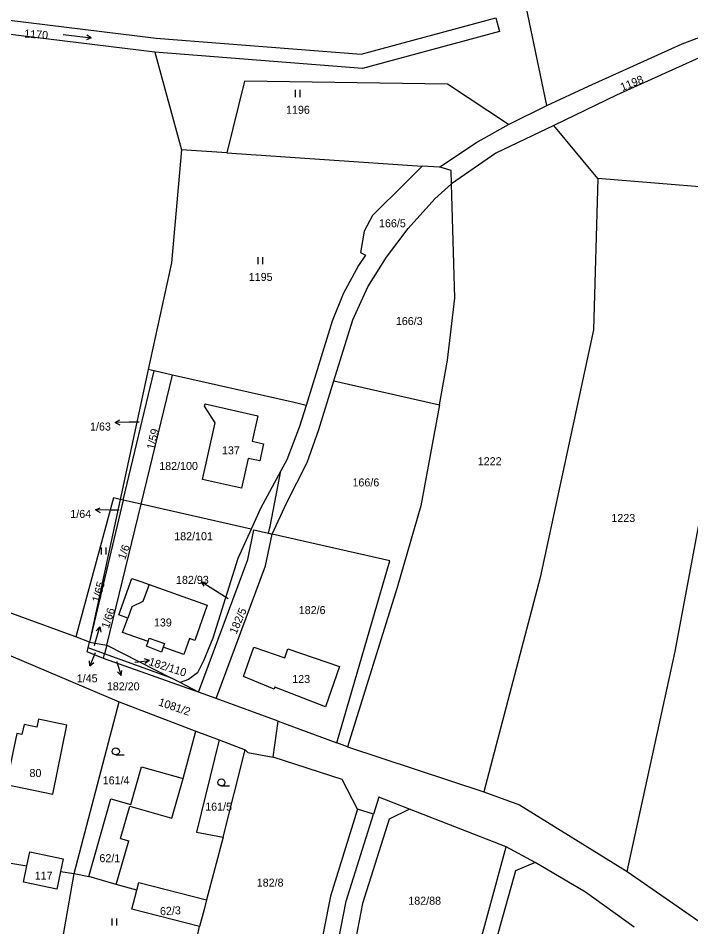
# Model space of a CAD drawing. Extents: x -746176 to -739709, y -1128407 to -1124482.
# Drawn here: x -742008.2 to -741865.4, y -1126433.2 to -1126240.2 of the extents above; entities that cross this region are included whole.
import ezdxf

# ---------------------------------------------------------------- set-up
doc = ezdxf.new("R2010")
doc.units = 0
for name, color, linetype in [('Vrstva 33', 7, 'Continuous'), ('Vrstva 42', 7, 'Continuous'), ('Vrstva 43', 7, 'Continuous'), ('Vrstva 44', 7, 'Continuous'), ('Vrstva 47', 7, 'Continuous')]:
    doc.layers.add(name, color=color, linetype=linetype)

msp = doc.modelspace()

# ---------------------------------------------------------------- linework, layer by layer
at = {"layer": 'Vrstva 33'}
for p, q in [((-741979.16, -1126247.44), (-741973.49, -1126268.18)), ((-741904.1, -1126262.78), (-741895.95, -1126258.73)), ((-741885.09, -1126274.27), (-741894.45, -1126263.02)), ((-741963.91, -1126268.84), (-741973.49, -1126268.18)), ((-741963.91, -1126268.84), (-741922.39, -1126271.67)), ((-741918.69, -1126271.87), (-741922.39, -1126271.67)), ((-741856.86, -1126276.54), (-741885.09, -1126274.27)), ((-741980.55, -1126314.84), (-741986.51, -1126342.46)), ((-741985.86, -1126342.61), (-741979.32, -1126315.12)), ((-741982.09, -1126343.47), (-741975.4, -1126316.01)), ((-741979.32, -1126315.12), (-741980.55, -1126314.84)), ((-741975.4, -1126316.01), (-741979.32, -1126315.12)), ((-741941.15, -1126317.27), (-741918.74, -1126322.36)), ((-741951.16, -1126334.05), (-741952.39, -1126336.34)), ((-741952.39, -1126336.34), (-741956.73, -1126344.37)), ((-741986.51, -1126342.46), (-741993.03, -1126372.73)), ((-741985.86, -1126342.61), (-741993.03, -1126372.73)), ((-741989.38, -1126373.38), (-741982.09, -1126343.47)), ((-741985.86, -1126342.61), (-741986.51, -1126342.46)), ((-741982.09, -1126343.47), (-741985.86, -1126342.61)), ((-741958.73, -1126348.77), (-741982.09, -1126343.47)), ((-741954.27, -1126349.79), (-741951.24, -1126343.21)), ((-741956.73, -1126344.37), (-741958.73, -1126348.77)), ((-741955, -1126349.62), (-741954.27, -1126349.79)), ((-741993.03, -1126372.73), (-741995.94, -1126371.66)), ((-741993.33, -1126374), (-741993.03, -1126372.73)), ((-741989.85, -1126375.26), (-741993.33, -1126374)), ((-741993.03, -1126372.73), (-741989.38, -1126373.38)), ((-741989.38, -1126373.38), (-741989.85, -1126375.26)), ((-741989.38, -1126373.38), (-741975.79, -1126380.32)), ((-741990.09, -1126376.24), (-741989.85, -1126375.26)), ((-741969.88, -1126383.35), (-741990.09, -1126376.24)), ((-741975.79, -1126380.32), (-741989.85, -1126375.26)), ((-741973.78, -1126381.35), (-741975.79, -1126380.32)), ((-741972.03, -1126380.69), (-741973.78, -1126381.35)), ((-741969.88, -1126383.35), (-741973.78, -1126381.35)), ((-741966.13, -1126384.73), (-741969.88, -1126383.35)), ((-741996.32, -1126421.94), (-741986.71, -1126385.43)), ((-741986.71, -1126385.43), (-741970.45, -1126391.64)), ((-741953, -1126389.58), (-741966.13, -1126384.73)), ((-741954.07, -1126397.17), (-741953, -1126389.58)), ((-741953, -1126389.58), (-741940.51, -1126394.18)), ((-741970.45, -1126391.64), (-741965.53, -1126393.52)), ((-741965.53, -1126393.52), (-741959.96, -1126395.65)), ((-741964.66, -1126414.2), (-741959.96, -1126395.65)), ((-741938.23, -1126394.97), (-741940.51, -1126394.18)), ((-741938.23, -1126394.97), (-741909.32, -1126404.54)), ((-741932.77, -1126409.29), (-741936.11, -1126408.24)), ((-741904.57, -1126416.23), (-741925.07, -1126408.25)), ((-741964.66, -1126414.2), (-741968.2, -1126427.52)), ((-741898.42, -1126419.6), (-741904.57, -1126416.23)), ((-741999.2, -1126421.47), (-741996.32, -1126421.94)), ((-741999.11, -1126438.17), (-741996.32, -1126421.94)), ((-741996.32, -1126421.94), (-741993.21, -1126422.56)), ((-741878.88, -1126421.46), (-741852.49, -1126439.8)), ((-741971.96, -1126443.41), (-741969.67, -1126433.17))]:
    msp.add_line(p, q, dxfattribs=at)
for points in [[(-741895.95, -1126258.73), (-741902.39, -1126227.83), (-742032.39, -1126201.61)], [(-741979.16, -1126247.44), (-742018.02, -1126242.67), (-742051.56, -1126236.78), (-742071.8, -1126233.98)], [(-742037.23, -1126236.37), (-742017.58, -1126239.71), (-741978.86, -1126244.46), (-741935.37, -1126247.86), (-741906.75, -1126240.11), (-741905.97, -1126243.01), (-741935.09, -1126250.9), (-741979.16, -1126247.44)], [(-741895.95, -1126258.73), (-741887.06, -1126254.64), (-741867.23, -1126245.63), (-741859.7, -1126242.83), (-741853.68, -1126241.82), (-741840.1, -1126242.23)], [(-741841.74, -1126251.46), (-741852.27, -1126246.05), (-741856.49, -1126246.25), (-741862.01, -1126247.91), (-741881.16, -1126256.56), (-741894.45, -1126263.02)], [(-741904.1, -1126262.78), (-741917.02, -1126254.2), (-741960.14, -1126253.61), (-741963.91, -1126268.84)], [(-741918.69, -1126271.87), (-741911.03, -1126266.72), (-741904.1, -1126262.78)], [(-741894.45, -1126263.02), (-741906.75, -1126268.89), (-741916.15, -1126275.4)], [(-741973.49, -1126268.18), (-741975.66, -1126292.15), (-741980.55, -1126314.84)], [(-741922.39, -1126271.67), (-741925.91, -1126275.15), (-741932.95, -1126282.11), (-741934.69, -1126285.47), (-741935.47, -1126289.95), (-741934.45, -1126290.55), (-741935.93, -1126292.73), (-741939.16, -1126298.76), (-741941.48, -1126304.55), (-741947.05, -1126322.45)], [(-741916.15, -1126275.4), (-741916.23, -1126272.57), (-741918.37, -1126271.96), (-741918.69, -1126271.87)], [(-741941.15, -1126317.27), (-741937.11, -1126304.31), (-741933.93, -1126297.28), (-741929.99, -1126290.94), (-741925.39, -1126284.87), (-741919.74, -1126278.55), (-741916.15, -1126275.4)], [(-741918.74, -1126322.36), (-741917, -1126312.88), (-741915.44, -1126299.69), (-741916.15, -1126275.4)], [(-741885.09, -1126274.27), (-741886, -1126306.44), (-741897.34, -1126359), (-741909.32, -1126404.54)], [(-741878.88, -1126421.46), (-741868.71, -1126374.72), (-741857.4, -1126314.53), (-741856.86, -1126276.54)], [(-741947.05, -1126322.45), (-741949.55, -1126321.88), (-741975.4, -1126316.01)], [(-741951.24, -1126343.21), (-741946.82, -1126334.61), (-741944.36, -1126327.59), (-741941.15, -1126317.27)], [(-741969.03, -1126338.22), (-741966.34, -1126326.2), (-741968.61, -1126322.66), (-741968.49, -1126322.14), (-741957.3, -1126324.7), (-741958.52, -1126330.09), (-741956.07, -1126330.63), (-741956.89, -1126334.27), (-741959.34, -1126333.71), (-741960.77, -1126340.08), (-741969.03, -1126338.22)], [(-741947.05, -1126322.45), (-741948.46, -1126326.96), (-741951.16, -1126334.05)], [(-741918.74, -1126322.36), (-741922.66, -1126343.77), (-741927.73, -1126361.18), (-741938.23, -1126394.97)], [(-741955, -1126349.62), (-741954.81, -1126348.66), (-741954.71, -1126348.16), (-741952.39, -1126336.34)], [(-741986.51, -1126342.46), (-741987.96, -1126342.12), (-741995.94, -1126371.66)], [(-741958.73, -1126348.77), (-741961.57, -1126355.01), (-741966.88, -1126371.94), (-741968.84, -1126376.73), (-741970.09, -1126379.3), (-741972.03, -1126380.69)], [(-741969.88, -1126383.35), (-741959.42, -1126355.18), (-741958.17, -1126348.9), (-741955, -1126349.62)], [(-741966.13, -1126384.73), (-741955.67, -1126356.57), (-741954.27, -1126349.79)], [(-741940.51, -1126394.18), (-741929.25, -1126355.48), (-741954.27, -1126349.79)], [(-741977.77, -1126374.86), (-741980.95, -1126373.62), (-741980.61, -1126372.64), (-741986.02, -1126370.7), (-741984.92, -1126367.63), (-741986.82, -1126366.94), (-741984.02, -1126359.21), (-741982.15, -1126359.85), (-741980.39, -1126360.49), (-741968.02, -1126364.9), (-741970.7, -1126372.41), (-741971.84, -1126372), (-741973.03, -1126375.35), (-741977.37, -1126373.8), (-741977.77, -1126374.86)], [(-741995.94, -1126371.66), (-741996.93, -1126371.29), (-742011.08, -1126366.08), (-742011.25, -1126365.95)], [(-742017.65, -1126371.11), (-742017.02, -1126371.6), (-742014.99, -1126373.44), (-741986.71, -1126385.43)], [(-741990.09, -1126376.24), (-741993.53, -1126374.84), (-741993.33, -1126374)], [(-741958.18, -1126373.85), (-741951.58, -1126376.12), (-741950.91, -1126374.18), (-741939.97, -1126377.94), (-741942.91, -1126386.52), (-741953.71, -1126382.33), (-741953.86, -1126382.76), (-741960.32, -1126380.06), (-741958.18, -1126373.85)], [(-742003.87, -1126389.15), (-742004.21, -1126390.8), (-742006.94, -1126390.24), (-742007.38, -1126392.41), (-742008.47, -1126392.19), (-742010.7, -1126403.03), (-742000.83, -1126405.05), (-741997.82, -1126390.4), (-742003.87, -1126389.15)], [(-741993.21, -1126422.56), (-741988.52, -1126406.06), (-741984.26, -1126407.27), (-741981.98, -1126399.24), (-741973.18, -1126401.74), (-741970.45, -1126391.64)], [(-741965.53, -1126393.52), (-741970.31, -1126413.16), (-741964.66, -1126414.2)], [(-741959.96, -1126395.65), (-741959.39, -1126396.19), (-741954.07, -1126397.17)], [(-741936.11, -1126408.24), (-741939.36, -1126401.91), (-741954.07, -1126397.17)], [(-741909.32, -1126404.54), (-741901.76, -1126407.3), (-741878.88, -1126421.46)], [(-741925.07, -1126408.25), (-741931.64, -1126405.69), (-741932.77, -1126409.29)], [(-741954.32, -1126508.73), (-741938.56, -1126427.78), (-741932.77, -1126409.29)], [(-741936.11, -1126408.24), (-741941.9, -1126426.74), (-741946.15, -1126448.52)], [(-741925.07, -1126408.25), (-741929.41, -1126410.36), (-741935.06, -1126428.26), (-741937.58, -1126441.15)], [(-742024.68, -1126414.24), (-742015.91, -1126416.77), (-742016.26, -1126418.65), (-742006.36, -1126420.29)], [(-741912.45, -1126446.2), (-741911.72, -1126442.48), (-741904.57, -1126416.23)], [(-742006.36, -1126420.29), (-742005.72, -1126417.27), (-741998.63, -1126418.76), (-741999.2, -1126421.47)], [(-741999.2, -1126421.47), (-741999.99, -1126425.22), (-742007.08, -1126423.73), (-742006.36, -1126420.29)], [(-741898.42, -1126419.6), (-741902.57, -1126421.34), (-741908.84, -1126443.59), (-741914.46, -1126471.66), (-741921.58, -1126508.41), (-741929.05, -1126550.68), (-741935.86, -1126591.95), (-741938.82, -1126591.67)], [(-741877.38, -1126433.3), (-741887.7, -1126425.84), (-741898.42, -1126419.6)], [(-741983.01, -1126425.46), (-741987.35, -1126424.23), (-741993.21, -1126422.56)], [(-741983.01, -1126425.46), (-741982.58, -1126423.8), (-741968.2, -1126427.52)], [(-741969.67, -1126433.17), (-741984.04, -1126429.45), (-741983.01, -1126425.46)], [(-741968.2, -1126427.52), (-741968.72, -1126429.53), (-741969.67, -1126433.17)]]:
    msp.add_lwpolyline(points, dxfattribs=at)
at = {"layer": 'Vrstva 43'}
for p, q in [((-741987.6, -1126326.08), (-741986.61, -1126325.56)), ((-741984.6, -1126326.03), (-741987.6, -1126326.08)), ((-741987.6, -1126326.08), (-741986.59, -1126326.57)), ((-741982.49, -1126326), (-741984.6, -1126326.03)), ((-741991.75, -1126344.68), (-741990.74, -1126344.19)), ((-741988.75, -1126344.73), (-741991.75, -1126344.68)), ((-741991.75, -1126344.68), (-741990.76, -1126345.2)), ((-741986.71, -1126344.75), (-741988.75, -1126344.73)), ((-741966.82, -1126361.51), (-741969.36, -1126359.92)), ((-741969.36, -1126359.92), (-741968.25, -1126360.03)), ((-741969.36, -1126359.92), (-741968.78, -1126360.88)), ((-741963.58, -1126363.54), (-741966.82, -1126361.51)), ((-741991.68, -1126372.43), (-741990.85, -1126369.54)), ((-741990.85, -1126369.54), (-741991.61, -1126370.37)), ((-741990.85, -1126369.54), (-741990.65, -1126370.65)), ((-741991.98, -1126373.5), (-741991.68, -1126372.43)), ((-741991.82, -1126375.03), (-741992.94, -1126377.81)), ((-741980.33, -1126376.66), (-741981.39, -1126376.29)), ((-741992.94, -1126377.81), (-741993.03, -1126376.7)), ((-741992.94, -1126377.81), (-741992.1, -1126377.07)), ((-741987.25, -1126376.89), (-741987.22, -1126377)), ((-741987.22, -1126377), (-741986.34, -1126379.87)), ((-741983.4, -1126377.04), (-741983.31, -1126377.03)), ((-741983.31, -1126377.03), (-741980.33, -1126376.66)), ((-741980.33, -1126376.66), (-741981.26, -1126377.28)), ((-741986.34, -1126379.87), (-741987.11, -1126379.06)), ((-741986.34, -1126379.87), (-741986.16, -1126378.77))]:
    msp.add_line(p, q, dxfattribs=at)
at = {"layer": 'Vrstva 44'}
for p, q in [((-741998.62, -1126243.68), (-741992.67, -1126244.41)), ((-741992.67, -1126244.41), (-741993.7, -1126244.78)), ((-741992.67, -1126244.41), (-741993.58, -1126243.79)), ((-741949.31, -1126256.96), (-741949.31, -1126255.46)), ((-741948.31, -1126256.96), (-741948.31, -1126255.46)), ((-741957.22, -1126292.47), (-741957.22, -1126290.97)), ((-741956.22, -1126292.47), (-741956.22, -1126290.97)), ((-741990.47, -1126354.15), (-741990.47, -1126352.65)), ((-741989.47, -1126354.15), (-741989.47, -1126352.65)), ((-741987.45, -1126396.72), (-741985.7, -1126396.72)), ((-741965.03, -1126403.31), (-741963.28, -1126403.31)), ((-741988.21, -1126432.96), (-741988.21, -1126431.46)), ((-741987.21, -1126432.96), (-741987.21, -1126431.46))]:
    msp.add_line(p, q, dxfattribs=at)
for centre in [(-741987.45, -1126395.97), (-741965.03, -1126402.56)]:
    msp.add_circle(centre, 0.75, dxfattribs=at)
at = {"layer": 'Vrstva 47'}
for p, q in [((-741980.39, -1126360.49), (-741981.73, -1126364.15)), ((-741981.73, -1126364.15), (-741984.06, -1126365.24)), ((-741984.06, -1126365.24), (-741984.92, -1126367.63)), ((-741980.61, -1126372.64), (-741980.36, -1126371.92)), ((-741980.36, -1126371.92), (-741977.1, -1126373.07)), ((-741977.1, -1126373.07), (-741977.37, -1126373.8)), ((-741975.58, -1126410.16), (-741973.18, -1126401.74)), ((-741986.43, -1126414.45), (-741984.48, -1126407.62)), ((-741984.48, -1126407.62), (-741975.58, -1126410.16)), ((-741987.35, -1126424.23), (-741984.7, -1126414.94)), ((-741986.43, -1126414.45), (-741984.7, -1126414.94))]:
    msp.add_line(p, q, dxfattribs=at)

# ---------------------------------------------------------------- texts
at = {"layer": 'Vrstva 42'}
for s, rotation, p in [('1170', 356, (-742006.94, -1126244.31)), ('1198', 22, (-741879.92, -1126255.73)), ('1/59', 77, (-741979.28, -1126331.96)), ('1/6', 70, (-741985.5, -1126355.38)), ('1/65', 75, (-741990.9, -1126364.43)), ('1/66', 72, (-741988.95, -1126370.01)), ('182/5', 67, (-741961.85, -1126371.18)), ('182/110', 342, (-741980.61, -1126377.58)), ('1081/2', 341, (-741978.54, -1126386.16)), ('62/3', 3, (-741978.03, -1126430.78))]:
    msp.add_text(s, height=1.7, rotation=rotation, dxfattribs=at).set_placement(p)
for s, p in [('1196', (-741951.31, -1126260.51)), ('166/5', (-741931.57, -1126284.62)), ('1195', (-741959.22, -1126296.02)), ('166/3', (-741927.99, -1126305.39)), ('1/63', (-741992.92, -1126327.81)), ('137', (-741964.91, -1126332.86)), ('1222', (-741910.6, -1126335.17)), ('182/100', (-741978.23, -1126336.18)), ('166/6', (-741937.2, -1126339.68)), ('1/64', (-741997.11, -1126346.37)), ('1223', (-741882.23, -1126347.23)), ('182/101', (-741975.05, -1126351.11)), ('182/93', (-741974.67, -1126360.38)), ('182/6', (-741948.61, -1126366.8)), ('139', (-741979.36, -1126369.43)), ('1/45', (-741995.74, -1126381.29)), ('123', (-741949.99, -1126381.44)), ('182/20', (-741989.35, -1126383)), ('80', (-742005.78, -1126401.4)), ('161/4', (-741990.23, -1126402.97)), ('161/5', (-741968.47, -1126408.56)), ('62/1', (-741990.93, -1126419.5)), ('117', (-742004.67, -1126423.21)), ('182/8', (-741957.53, -1126424.69)), ('182/88', (-741925.35, -1126428.54))]:
    msp.add_text(s, height=1.7, dxfattribs=at).set_placement(p)

doc.saveas('drawing.dxf')
